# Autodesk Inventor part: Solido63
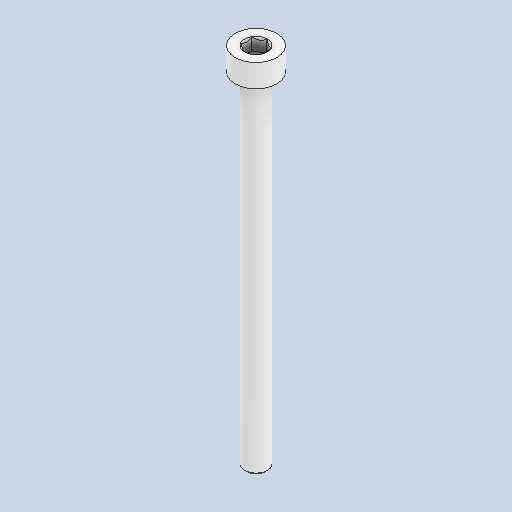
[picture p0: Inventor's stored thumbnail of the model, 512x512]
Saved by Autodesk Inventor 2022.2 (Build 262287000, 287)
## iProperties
Created: 2024-10
Part Number: Solido63
Material: Generico
Document SubType Name: Modeling
Designer: 18907419
Density: 1 g/cm^3
Appearance: Default
Author: 18907419
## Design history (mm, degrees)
feature "Solido63"
node "Solido1"
